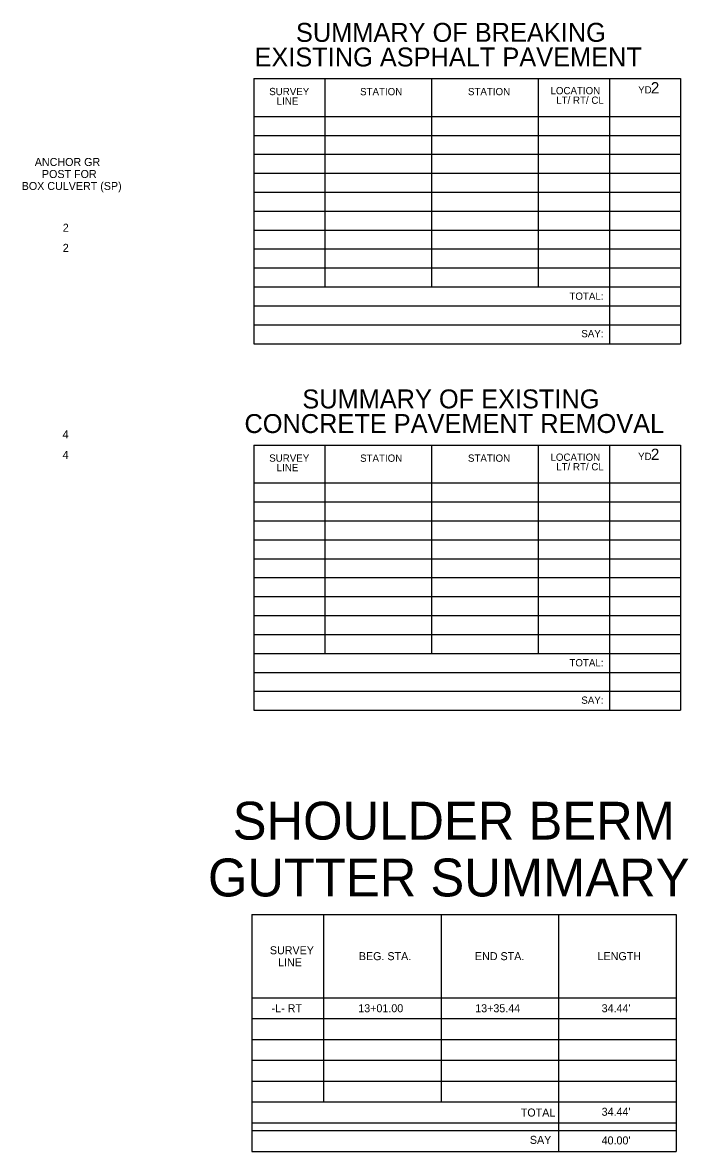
# Model space of a CAD drawing. Extents: x 1852861 to 1855026, y 258638 to 259806.
# Drawn here: x 1854587 to 1855026, y 258867 to 259612 of the extents above; entities that cross this region are included whole.
import ezdxf

# ---------------------------------------------------------------- set-up
doc = ezdxf.new("R2010")
doc.units = 0
for name, color, linetype in [('Sheet Summary Combination CELL', 7, 'Continuous'), ('Sheet Summary Combination Grid CELL', 7, 'Continuous'), ('Sheet Summary Guardrail CELL', 7, 'Continuous')]:
    doc.layers.add(name, color=color, linetype=linetype)

msp = doc.modelspace()

# ---------------------------------------------------------------- linework, layer by layer
at = {"layer": 'Sheet Summary Combination CELL'}
for p, q in [((1854881.1, 259575.48), (1854881.1, 259575.48)), ((1854887.35, 259575.38), (1854887.35, 259575.38)), ((1854896.4, 259575.58), (1854896.4, 259575.58)), ((1854902, 259575.48), (1854902, 259575.48)), ((1854881.1, 259333.56), (1854881.1, 259333.56)), ((1854887.35, 259333.46), (1854887.35, 259333.46)), ((1854896.4, 259333.66), (1854896.4, 259333.66)), ((1854902, 259333.56), (1854902, 259333.56))]:
    msp.add_line(p, q, dxfattribs=at)
at = {"layer": 'Sheet Summary Combination Grid CELL'}
for p, q in [((1854739.85, 259575.53), (1855021.2, 259575.53)), ((1854739.85, 259575.53), (1854739.85, 259400.53)), ((1854786.75, 259575.53), (1854786.75, 259438.03)), ((1854857.1, 259575.53), (1854857.1, 259438.03)), ((1854927.4, 259575.53), (1854927.4, 259438.03)), ((1854974.3, 259575.53), (1854974.3, 259400.53)), ((1855021.2, 259575.53), (1855021.2, 259400.53)), ((1854739.85, 259550.53), (1855021.2, 259550.53)), ((1854739.85, 259538.03), (1855021.2, 259538.03)), ((1854739.85, 259525.53), (1855021.2, 259525.53)), ((1854739.85, 259513.03), (1855021.2, 259513.03)), ((1854739.85, 259500.53), (1855021.2, 259500.53)), ((1854739.85, 259488.03), (1855021.2, 259488.03)), ((1854739.85, 259475.53), (1855021.2, 259475.53)), ((1854739.85, 259463.03), (1855021.2, 259463.03)), ((1854739.85, 259450.53), (1855021.2, 259450.53)), ((1854739.85, 259438.03), (1855021.2, 259438.03)), ((1854739.85, 259425.53), (1855021.2, 259425.53)), ((1854739.85, 259413.03), (1855021.2, 259413.03)), ((1854739.85, 259400.53), (1855021.2, 259400.53)), ((1854739.85, 259333.61), (1855021.2, 259333.61)), ((1854739.85, 259333.61), (1854739.85, 259158.61)), ((1854786.75, 259333.61), (1854786.75, 259196.11)), ((1854857.1, 259333.61), (1854857.1, 259196.11)), ((1854927.4, 259333.61), (1854927.4, 259196.11)), ((1854974.3, 259333.61), (1854974.3, 259158.61)), ((1855021.2, 259333.61), (1855021.2, 259158.61)), ((1854739.85, 259308.61), (1855021.2, 259308.61)), ((1854739.85, 259296.11), (1855021.2, 259296.11)), ((1854739.85, 259283.61), (1855021.2, 259283.61)), ((1854739.85, 259271.11), (1855021.2, 259271.11)), ((1854739.85, 259258.61), (1855021.2, 259258.61)), ((1854739.85, 259246.11), (1855021.2, 259246.11)), ((1854739.85, 259233.61), (1855021.2, 259233.61)), ((1854739.85, 259221.11), (1855021.2, 259221.11)), ((1854739.85, 259208.61), (1855021.2, 259208.61)), ((1854739.85, 259196.11), (1855021.2, 259196.11)), ((1854739.85, 259183.61), (1855021.2, 259183.61)), ((1854739.85, 259171.11), (1855021.2, 259171.11)), ((1854739.85, 259158.61), (1855021.2, 259158.61))]:
    msp.add_line(p, q, dxfattribs=at)
at = {"layer": 'Sheet Summary Guardrail CELL'}
for p, q in [((1854738.42, 259023.79), (1855018.37, 259023.79)), ((1854738.42, 259023.79), (1854738.42, 258867.42)), ((1854785.72, 259023.79), (1854785.72, 258900.04)), ((1854863.27, 259023.79), (1854863.27, 258900.04)), ((1854940.82, 259023.79), (1854940.82, 258867.42)), ((1855018.37, 259023.79), (1855018.37, 258867.42)), ((1854738.42, 258968.79), (1855018.37, 258968.79)), ((1854738.42, 258955.04), (1855018.37, 258955.04)), ((1854738.42, 258941.29), (1855018.37, 258941.29)), ((1854738.42, 258927.54), (1855018.37, 258927.54)), ((1854738.42, 258913.79), (1855018.37, 258913.79)), ((1854738.42, 258900.04), (1855018.37, 258900.04)), ((1854738.42, 258886.29), (1855018.37, 258886.29)), ((1854738.42, 258881.17), (1855018.37, 258881.17)), ((1854738.42, 258867.42), (1855018.37, 258867.42))]:
    msp.add_line(p, q, dxfattribs=at)

# ---------------------------------------------------------------- texts
at = {"layer": 'Sheet Summary Combination CELL'}
for s, p in [('SUMMARY OF BREAKING', (1854767.62, 259599.72)), ('EXISTING ASPHALT PAVEMENT', (1854740.27, 259583.47)), ('SUMMARY OF EXISTING', (1854771.81, 259357.8)), ('CONCRETE PAVEMENT REMOVAL', (1854733.66, 259341.54))]:
    msp.add_text(s, height=12.5001, rotation=0.01193, dxfattribs=at).set_placement(p)
for s, p in [('SURVEY', (1854749.99, 259564.55)), ('STATION', (1854809.9, 259564.49)), ('STATION', (1854881.04, 259564.51)), ('LOCATION', (1854935.45, 259565.13)), ('LINE', (1854754.9, 259558.25)), ('LT/ RT/ CL', (1854939.24, 259558.83)), ('TOTAL:', (1854947.95, 259429.48)), ('SAY:', (1854955.79, 259404.77)), ('SURVEY', (1854749.99, 259322.63)), ('STATION', (1854809.9, 259322.57)), ('STATION', (1854881.04, 259322.59)), ('LOCATION', (1854935.45, 259323.21)), ('LT/ RT/ CL', (1854939.24, 259316.91)), ('LINE', (1854754.9, 259316.33)), ('TOTAL:', (1854947.95, 259187.56)), ('SAY:', (1854955.79, 259162.85))]:
    msp.add_text(s, height=4.8, dxfattribs=at).set_placement(p)
at = {"layer": 'Sheet Summary Combination Grid CELL'}
for s, height, p in [('YD', 4.8, (1854993.25, 259565.65)), ('2', 7.5, (1855001.63, 259565.65)), ('2', 7.5, (1855001.63, 259323.74)), ('YD', 4.8, (1854993.25, 259323.74))]:
    msp.add_text(s, height=height, dxfattribs=at).set_placement(p)
at = {"layer": 'Sheet Summary Guardrail CELL'}
for s, height, p in [('ANCHOR GR', 5.28, (1854595.38, 259517.8)), ('POST FOR', 5.28, (1854600.09, 259509.88)), ('BOX CULVERT (SP)', 5.28, (1854586.76, 259501.96)), ('2', 5.28, (1854613.85, 259474.4)), ('2', 5.28, (1854613.85, 259461.13)), ('4', 5.28, (1854613.7, 259338.02)), ('4', 5.28, (1854613.7, 259324.48)), ('SHOULDER BERM', 24.9999, (1854725.9, 259073.21)), ('GUTTER SUMMARY', 24.9999, (1854709.56, 259035.71)), ('SURVEY', 5.28, (1854750.41, 258997.55)), ('LINE', 5.28, (1854755.8, 258989.63)), ('BEG. STA.', 5.28, (1854809.09, 258993.65)), ('END STA.', 5.28, (1854885.65, 258993.65)), ('LENGTH', 5.28, (1854966.53, 258993.65)), ('-L- RT', 5.28, (1854751.56, 258959.27)), ('13+01.00', 5.28, (1854808.71, 258959.27)), ('13+35.44', 5.28, (1854885.82, 258959.27)), ("34.44'", 5.28, (1854969.18, 258959.27)), ('TOTAL', 5.28, (1854915.87, 258890.44)), ("34.44'", 5.28, (1854969.18, 258890.96)), ('SAY', 5.28, (1854921.87, 258872.42)), ("40.00'", 5.28, (1854969.18, 258872.05))]:
    msp.add_text(s, height=height, dxfattribs=at).set_placement(p)

doc.saveas('drawing.dxf')
